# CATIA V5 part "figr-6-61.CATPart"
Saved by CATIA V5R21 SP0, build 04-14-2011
Part number: Part1
Bounding box of the stored display mesh (mm): x -50.648 to 50.648, y -72.183 to 72.183, z -40 to 40
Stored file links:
  D:\CATIA V5R21 E-RESOURCES\CATIA-V5R21\catia-v5r21-prt\c06-catia-v5r21-prt\c06-catia-v5r21-figr-6-61.CATPart
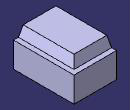
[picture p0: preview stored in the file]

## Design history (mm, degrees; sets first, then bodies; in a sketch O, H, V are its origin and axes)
Set1
  Plane1: type Offset, RefPlane xy-plane, Offset 20
Body1 (main body)
  Sketch1 on xy-plane, origin (0, 0, 0), H (1, 0, 0), V (0, 1, 0)
    line L1 (-50.6478, 72.1832) -> (50.6478, 72.1832)
    line L2 (50.6478, 72.1832) -> (50.6478, -72.1832)
    line L3 (50.6478, -72.1832) -> (-50.6478, -72.1832)
    line L4 (-50.6478, -72.1832) -> (-50.6478, 72.1832)
    axis line L5 (50.6478, -72.1832) -> (-50.6478, 72.1832)
    horizontal: L1 H, L3 H
    vertical: L2 V, L4 V
    midpoint: O L5
  Pad1: profile Sketch1, direction (0, 0, 1), length 40, mirrored extent
  Draft1: Angle 30, Neutral xy-plane, Parting Plane1, PullDir (0, 0, 1), SupportToDraft (face of Pad1; face of Pad1)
